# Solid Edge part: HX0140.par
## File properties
Author: felixr
Template: Iso Metric Part.par
Last saved by: felixr
Revision: 78
Application: Solid Edge
Document Number: HX0166
Accuracy: 0.990
Username: felixr
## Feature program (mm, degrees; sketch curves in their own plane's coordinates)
sketch for "unnamed Protrusion 1" plane through (0, 0, 0) normal (0, 0, 1) x-axis (1, 0, 0)
  line (-15, -15.75) -> (15, -15.75)
  line (15, -15.75) -> (15, 15.75)
  line (15, 15.75) -> (-15, 15.75)
  line (-15, 15.75) -> (-15, -15.75)
  dimension (linear) = 15
  dimension (linear) = 15
extrude "unnamed Protrusion 1" add finite 25.6 along +normal
fillet "Round_1" radius 3
sketch for "ExtrudedProtrusion_2" plane through (0, 0, 25.6) normal (0, 0, 1) x-axis (1, 0, 0)
  line (-15, -9.3) -> (15, -9.3)
  line (15, -9.3) -> (15, 9.3)
  line (15, 9.3) -> (-15, 9.3)
  line (-15, 9.3) -> (-15, -9.3)
  dimension (linear) = 15
  dimension (linear) = 15
extrude "ExtrudedProtrusion_2" add finite 20.9 along +normal
fillet "unnamed Round 1"
sketch for "unnamed Cutout 1" plane through (0, -9.3, 36.3) normal (0, -1, 0) x-axis (1, 0, 0)
  line (-8, -10.7) -> (8, -10.7)
  line (8, -10.7) -> (8, 2.3)
  line (8, 2.3) -> (-8, 2.3)
  line (-8, 2.3) -> (-8, -10.7)
  dimension (linear) = 8
  dimension (linear) = 8
extrude "unnamed Cutout 1" cut through along -normal
sketch for "ExtrudedCutout_2" plane through (0, -15.75, 13) normal (0, -1, 0) x-axis (1, 0, 0)
  line (-8, 9.6) -> (8, 9.6)
  line (8, 9.6) -> (8, 19.6)
  line (8, 19.6) -> (-8, 19.6)
  line (-8, 19.6) -> (-8, 9.6)
extrude "ExtrudedCutout_2" cut finite 40 along -normal
fillet "Round_3" radius 7
sketch for "ExtrudedProtrusion_4" plane through (0, -15.75, 13) normal (0, -1, 0) x-axis (1, 0, 0)
  line (-2.5, -12.5) -> (2.5, -12.5)
  line (2.5, -12.5) -> (2.5, -10.5)
  line (2.5, -10.5) -> (-2.5, -10.5)
  line (-2.5, -10.5) -> (-2.5, -12.5)
extrude "ExtrudedProtrusion_4" add finite 32 along +normal
sketch for "unnamed Cutout 2" #1 plane through (0, -47.75, 1) normal (0, -1, 0) x-axis (1, 0, 0)
  line (0, 1) -> (0.6043, 1.1916)
  line (-0.6043, 1.1916) -> (0, 1)
  arc centre (0, 3.0981) radius 2 from (-0.6043, 1.1916) to (-1, 1.366) cw
  line (-0.6043, -0.1916) -> (0, 0)
  line (0.6043, -0.1916) -> (0, 0)
  arc centre (0, -2.0981) radius 2 from (0.6043, -0.1916) to (1, -0.366) cw
sketch for "unnamed Cutout 2" #2 plane through (0, -47.75, 1) normal (0, -1, 0) x-axis (1, 0, 0)
  line (-2.75, -1) -> (2.75, -1)
  line (2.75, -1) -> (2.75, 2)
  line (2.75, 2) -> (-2.75, 2)
  line (-2.75, 2) -> (-2.75, -1)
extrude "unnamed Cutout 2" cut
sketch for "ExtrudedCutout_4" plane through (0, -15.75, 13) normal (0, -1, 0) x-axis (1, 0, 0)
  line (-2.65, -13) -> (2.65, -13)
  line (2.65, -13) -> (2.65, -10)
  line (2.65, -10) -> (-2.65, -10)
  line (-2.65, -10) -> (-2.65, -13)
  dimension (linear) = 2.65
  dimension (linear) = 2.65
extrude "ExtrudedCutout_4" cut finite 1 along -normal
sketch for "ExtrudedProtrusion_5" #1 plane through (0, -47.75, 1.5) normal (0, -1, 0) x-axis (0.953254, 0, 0.302169)
  circle centre (-1.4299, 0.4533) radius 0.5511
sketch for "ExtrudedProtrusion_5" #2 plane through (0, -47.75, 1.5) normal (0, -1, 0) x-axis (0.953254, 0, 0.302169)
  circle centre (1.4299, -0.4533) radius 0.5511
extrude "ExtrudedProtrusion_5" add finite 6 along +normal
sketch for "ExtrudedProtrusion_6" plane through (0, -15.75, 13) normal (0, -1, 0) x-axis (1, 0, 0)
  line (-2, 7.6) -> (2, 7.6)
  line (2, 7.6) -> (2, 9.6)
  line (-2, 9.6) -> (2, 9.6)
  line (-2, 9.6) -> (-2, 7.6)
extrude "ExtrudedProtrusion_6" add finite 4 along +normal
sketch for "ExtrudedProtrusion_7" plane through (0, -18.1, 20.6) normal (0, 0, -1) x-axis (-1, 0, 0)
  line (-2, -1.65) -> (2, -1.65)
  line (2, -1.65) -> (2, 0.35)
  line (2, 0.35) -> (-2, 0.35)
  line (-2, 0.35) -> (-2, -1.65)
  dimension (linear) = 2
extrude "ExtrudedProtrusion_7" add finite 3 along +normal
mirror "unnamed Mirror 1" of "ExtrudedProtrusion_7", "ExtrudedProtrusion_6"
pattern "unnamed Pattern 1"
sketch for "ExtrudedProtrusion_8" plane through (0, 0, 0) normal (0, -1, 0) x-axis (1, 0, 0)
  circle centre (-15, 25.6) radius 1
extrude "ExtrudedProtrusion_8" add finite 20 symmetric
sketch for "ExtrudedCutout_5" plane through (0, 0, 46.5) normal (0, 0, 1) x-axis (1, 0, 0)
  line (-1.15, -8.5) -> (1.15, -8.5)
  line (1.15, -8.5) -> (1.15, 8.5)
  line (1.15, 8.5) -> (-1.15, 8.5)
  line (-1.15, 8.5) -> (-1.15, -8.5)
  dimension (linear) = 1.15
  dimension (linear) = 1.15
extrude "ExtrudedCutout_5" cut finite 1.6 along -normal
sketch for "ExtrudedProtrusion_9" plane through (15, 0, 21.05) normal (1, 0, 0) x-axis (0, 1, 0)
  line (-7, -2.55) -> (7, -2.55)
  line (7, -2.55) -> (7, 11.45)
  line (7, 11.45) -> (3.25, 11.45)
  line (3.25, 4.45) -> (3.25, 11.45)
  line (-3.25, 4.45) -> (3.25, 4.45)
  line (-3.25, 11.45) -> (-3.25, 4.45)
  line (-3.25, 11.45) -> (-7, 11.45)
  line (-7, 11.45) -> (-7, -2.55)
  dimension (linear) = 3.25
extrude "ExtrudedProtrusion_9" add finite 1.8 along +normal
fillet "Round_4" radius 1
sketch for "unnamed Cutout 3" plane through (16.575, -7, 24.35) normal (0, -1, 0) x-axis (0, 0, -1)
  line (5.85, -0.775) -> (5.85, -1.575)
  line (2.8644, -1.575) -> (5.85, -1.575)
  line (2.8644, -1.575) -> (5.85, -0.775)
  dimension (linear) = 5.85
  dimension (linear) = 2.8644
extrude "unnamed Cutout 3" cut through along -normal
sketch for "Hole_1" plane through (0, 0, 0) normal (0, 0, -1) x-axis (-1, 0, 0)
  hole centre (12, 11.4) bore radius 1.35
  dimension (linear) = 12
hole "Hole_1" diameter 2.7 finite
sketch for "unnamed Hole 1" plane through (0, 0, 0) normal (0, 0, -1) x-axis (-1, 0, 0)
  hole centre (-12, 11.4) bore radius 1.35
hole "unnamed Hole 1" finite
pattern "unnamed Pattern 2" of "Hole_1", "unnamed Hole 1"
sketch for "ExtrudedCutout_7" plane through (0, 0, 0) normal (0, 0, -1) x-axis (1, 0, 0)
  line (-2.5, 3.25) -> (0, 7.25)
  line (0, 7.25) -> (2.5, 3.25)
  line (2.5, 3.25) -> (1.5, 3.25)
  line (1.5, 3.25) -> (1.5, -4.75)
  line (1.5, -4.75) -> (-1.5, -4.75)
  line (-1.5, -4.75) -> (-1.5, 3.25)
  line (-1.5, 3.25) -> (-2.5, 3.25)
  dimension (linear) = 1.5
  dimension (linear) = 1.5
  dimension (linear) = 1.5
extrude "ExtrudedCutout_7" cut finite 0.5 along -normal
sketch for "ExtrudedCutout_8" #2 plane through (0, 0, 0) normal (0, 0, -1) x-axis (1, 0, 0)
extrude "ExtrudedCutout_8" cut finite 0.5 along -normal
fillet "unnamed Round 2"
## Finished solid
Body 1: solid body, 111 faces, 296 edges, 192 vertices, 2 separate solids.
  Faces by surface: plane 88, cylinder 23
  Edges by curve: line 204, circle 56, spline 36
Bounding box of the edges (mm): 32.800 x 73.500 x 46.500, from (-16, -53.75, 0) to (16.8, 19.75, 46.5).
Cylindrical faces by radius (mm): R0.5511 x2, R1 x5, R1.35 x2, R2 x4, R3 x4, R4.5 x2, R7 x4
Planar faces by outward normal: +x 10, +y 13, +z 10, -x 12, -y 18, -z 13, oblique 12
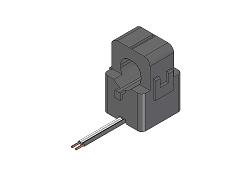
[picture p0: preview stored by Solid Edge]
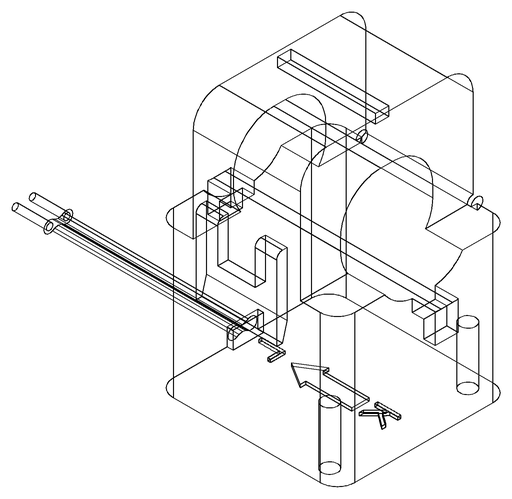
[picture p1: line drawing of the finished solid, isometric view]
